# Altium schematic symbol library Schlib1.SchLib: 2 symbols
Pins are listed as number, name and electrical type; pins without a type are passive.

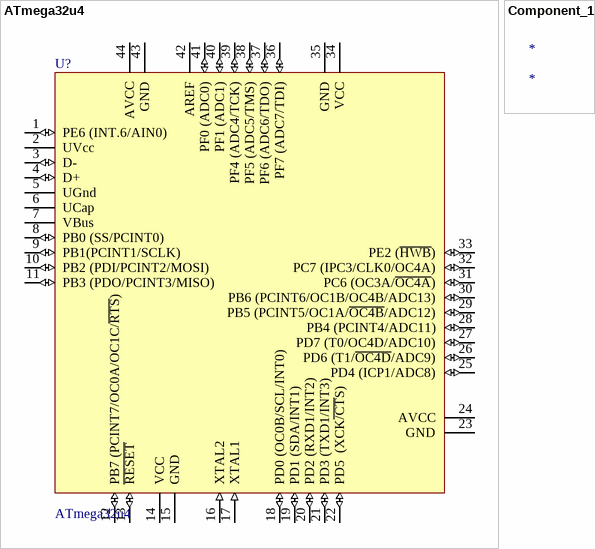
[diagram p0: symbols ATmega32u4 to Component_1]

## ATmega32u4
designator U?
8-Bit AVR Microcontroller with 32K Bytes of In-System Programmable Flash Memory
footprint 44A_N (Thin QFP, 44-Leads, Body 10x10mm, Pitch 0.8mm, IPC Medium Density)
3D model ATMEGA32-44A (44-Pin Thin Quad Flat Pack 0.8 mm Pitch)
pins: 1 PE6 (INT.6/AIN0) (io), 2 UVcc (power), 3 D- (io), 4 D+ (io), 5 UGnd (power), 6 UCap (power), 7 VBus (power), 8 PB0 (SS/PCINT0) (io), 9 PB1(PCINT1/SCLK) (io), 10 PB2 (PDI/PCINT2/MOSI) (io), 11 PB3 (PDO/PCINT3/MISO) (io), 12 PB7 (PCINT7/OC0A/OC1C/~{RTS}) (io), 13 ~{RESET} (io), 14 VCC (power), 15 GND (power), 16 XTAL2 (in), 17 XTAL1 (in), 18 PD0 (OC0B/SCL/INT0) (io), 19 PD1 (SDA/INT1) (io), 20 PD2 (RXD1/INT2) (io), 21 PD3 (TXD1/INT3) (io), 22 PD5  (XCK~{/CT}S) (io), 23 GND (power), 24 AVCC (power), 25 PD4 (ICP1/ADC8) (io), 26 PD6 (T1/~{OC4D}/ADC9) (io), 27 PD7 (T0/OC4D/ADC10) (io), 28 PB4 (PCINT4/ADC11) (io), 29 PB5 (PCINT5/OC1A/~{OC4B}/ADC12) (io), 30 PB6 (PCINT6/OC1B/OC4B/ADC13) (io), 31 PC6 (OC3A/~{OC4A}) (io), 32 PC7 (IPC3/CLK0/OC4A) (io), 33 PE2 (~{HWB}) (io), 34 VCC (power), 35 GND (power), 36 PF7 (ADC7/TDI) (io), 37 PF6 (ADC6/TDO) (io), 38 PF5 (ADC5/TMS) (io), 39 PF4 (ADC4/TCK) (io), 40 PF1 (ADC1) (io), 41 PF0 (ADC0) (io), 42 AREF (power), 43 GND (power), 44 AVCC (power)

## Component_1
designator *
